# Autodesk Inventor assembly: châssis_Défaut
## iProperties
Shininess: 64.0
Length Units: 11269
Angle Units: 11279
Time Units: 11290
Mass Units: 11283
Length Display Precision: 3
Angle Display Precision: 2
Compacted: True
Created: 2006-01
Part Number: châssis_Défaut
Document SubType Name: Assembly
Designer: riri
Density: 0.0
Volumn: 0.0
Area: 0.0
PropertySet Name: Model Information
Control State: 0
Master: False
Checked Out: False
Author: riri
